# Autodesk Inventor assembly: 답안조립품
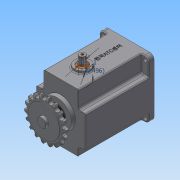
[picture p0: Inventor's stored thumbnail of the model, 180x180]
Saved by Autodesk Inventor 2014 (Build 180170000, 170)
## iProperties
Created: 2016-05
Part Number: 답안조립품
Document SubType Name: Assembly
Designer: 703-04
Author: 703-04
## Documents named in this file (16)
- C:\Users\703-04\Desktop\360508V1006\답안조립품.iam
- C:\Users\703-04\Desktop\360508V1006\본체.ipt
- C:\Users\703-04\Desktop\360508V1006\멈춤나사 M3x8.ipt
- C:\Users\703-04\Desktop\360508V1006\메인축.ipt
- C:\Users\703-04\Desktop\360508V1006\베어링 608.ipt
- C:\Users\703-04\Desktop\360508V1006\베어링 6003.ipt
- C:\Users\703-04\Desktop\360508V1006\볼트 M4 x 10.ipt
- C:\Users\703-04\Desktop\360508V1006\부시.ipt
- C:\Users\703-04\Desktop\360508V1006\서브축.ipt
- C:\Users\703-04\Desktop\360508V1006\스프로킷.ipt
- C:\Users\703-04\Desktop\360508V1006\슬라이더.ipt
- C:\Users\703-04\Desktop\360508V1006\커버.ipt
- C:\Users\703-04\Desktop\360508V1006\키 5 x 5 x 18.ipt
- C:\Users\703-04\Desktop\360508V1006\가변스프링.ipt
- C:\Users\703-04\Desktop\360508V1006\오일실 8 22 7.ipt
- C:\Users\703-04\Desktop\360508V1006\오일실 17 32 8.ipt
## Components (3 placed, 2 different names)
1. ISO 4762 M4 x 10:1
2. ISO 4762 M4 x 10:2
3. 가변스프링:1
